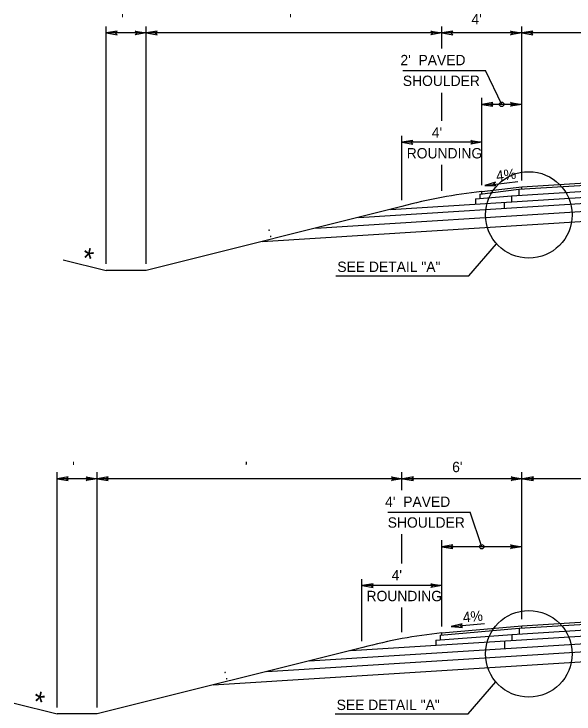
# Model space of a CAD drawing. Extents: x -592 to 1199, y -590 to 416.
# Drawn here: x -145.8 to -70.2, y -200.3 to -105.8 of the extents above; entities that cross this region are included whole.
import ezdxf

# ---------------------------------------------------------------- set-up
doc = ezdxf.new("R2010")
doc.units = 0
doc.layers.add('1', color=7, linetype='Continuous')
doc.layers.add('Des_ Drain_ Ftrs', color=7, linetype='Continuous')

msp = doc.modelspace()

# ---------------------------------------------------------------- linework, layer by layer
at = {"layer": '1'}
for p, q in [((-133.367, -139.572), (-133.367, -107.501)), ((-127.978, -139.572), (-127.978, -107.501)), ((-88.064, -110.502), (-88.064, -107.501)), ((-77.288, -128.298), (-77.288, -107.501)), ((-127.978, -108.381), (-133.367, -108.381)), ((-88.064, -108.381), (-127.978, -108.381)), ((-77.288, -108.381), (-88.064, -108.381)), ((-47.653, -108.381), (-77.288, -108.381)), ((-93.33, -113.449), (-82.189, -113.449)), ((-79.982, -118.031), (-82.189, -113.449)), ((-88.064, -120.251), (-88.064, -116.46)), ((-82.676, -128.932), (-82.676, -117.151)), ((-77.288, -118.031), (-82.676, -118.031)), ((-93.458, -130.942), (-93.458, -122.263)), ((-82.676, -123.143), (-93.453, -123.143)), ((-88.069, -129.71), (-88.069, -126.207)), ((-77.288, -129.176), (-47.653, -127.315)), ((-82.267, -128.973), (-77.799, -128.447)), ((-78.64, -130.37), (-47.653, -128.422)), ((-77.652, -129.499), (-47.653, -127.613)), ((-95.002, -132.208), (-47.653, -129.231)), ((-82.681, -129.813), (-77.288, -129.176)), ((-77.288, -129.476), (-77.288, -129.176)), ((-99.325, -133.288), (-47.653, -130.04)), ((-83.516, -130.803), (-78.64, -130.37)), ((-82.921, -130.142), (-77.652, -129.499)), ((-82.921, -130.142), (-82.921, -130.75)), ((-82.681, -130.113), (-82.681, -129.813)), ((-78.64, -130.37), (-78.64, -131.179)), ((-77.652, -129.499), (-77.652, -130.308)), ((-105.092, -134.73), (-47.653, -131.119)), ((-83.516, -130.803), (-83.516, -131.479)), ((-79.629, -131.241), (-79.629, -132.05)), ((-93.458, -131.822), (-127.978, -140.452)), ((-112.296, -136.531), (-47.653, -132.467)), ((-84.424, -141.157), (-80.685, -136.838)), ((-139.194, -138.995), (-133.367, -140.452)), ((-127.978, -140.452), (-133.367, -140.452)), ((-102.356, -141.157), (-84.424, -141.157)), ((-139.987, -199.449), (-139.987, -167.682)), ((-134.599, -199.449), (-134.599, -167.682)), ((-93.452, -170.111), (-93.452, -167.682)), ((-77.287, -187.549), (-77.287, -167.682)), ((-134.599, -168.562), (-139.987, -168.562)), ((-93.362, -168.562), (-134.599, -168.562)), ((-77.197, -168.562), (-93.362, -168.562)), ((-47.652, -168.562), (-77.197, -168.562)), ((-95.366, -173.077), (-84.225, -173.077)), ((-82.675, -177.748), (-84.225, -173.077)), ((-93.452, -180.019), (-93.452, -176.059)), ((-88.064, -188.506), (-88.064, -176.868)), ((-77.287, -177.748), (-88.064, -177.748)), ((-98.841, -190.512), (-98.841, -182.122)), ((-88.064, -183.002), (-98.84, -183.002)), ((-93.452, -189.283), (-93.452, -185.951)), ((-77.646, -188.746), (-47.652, -186.86)), ((-77.287, -188.423), (-47.652, -186.565)), ((-78.619, -189.603), (-47.652, -187.657)), ((-100.333, -191.765), (-47.652, -188.453)), ((-88.299, -189.707), (-77.646, -188.746)), ((-88.064, -189.386), (-77.287, -188.423)), ((-86.79, -188.513), (-82.309, -188.115)), ((-77.646, -188.746), (-77.646, -189.542)), ((-77.287, -188.723), (-77.287, -188.423)), ((-105.955, -193.17), (-47.652, -189.505)), ((-88.879, -190.361), (-78.619, -189.603)), ((-88.299, -189.707), (-88.299, -190.318)), ((-88.064, -189.686), (-88.064, -189.386)), ((-78.619, -189.603), (-78.619, -190.4)), ((-111.679, -194.601), (-47.652, -190.576)), ((-88.879, -190.361), (-88.879, -191.045)), ((-79.592, -190.461), (-79.592, -191.513)), ((-98.714, -191.36), (-134.599, -200.329)), ((-118.916, -196.41), (-47.652, -191.93)), ((-84.519, -200.298), (-80.779, -195.979)), ((-145.815, -198.873), (-139.987, -200.329)), ((-134.599, -200.329), (-139.987, -200.329)), ((-102.451, -200.298), (-84.519, -200.298))]:
    msp.add_line(p, q, dxfattribs=at)
for centre, radius in [((-79.982, -118.031), 0.3), ((-76.323, -132.955), 5.838), ((-82.675, -177.748), 0.3), ((-76.322, -192.207), 5.838)]:
    msp.add_circle(centre, radius, dxfattribs=at)
for centre, end in [((-75.799, -196.647), 105.23809), ((-81.181, -256.22), 105.12625)]:
    msp.add_arc(centre, 67.188, 95.87953, end, dxfattribs=at)
at = {"layer": 'Des_ Drain_ Ftrs'}
for points in [[(-133.367, -108.381), (-131.878, -108.629), (-132.173, -108.381), (-131.878, -108.133)], [(-127.978, -108.381), (-129.467, -108.629), (-129.172, -108.381), (-129.467, -108.133)], [(-127.978, -108.381), (-126.49, -108.629), (-126.785, -108.381), (-126.49, -108.133)], [(-88.064, -108.381), (-89.553, -108.629), (-89.258, -108.381), (-89.553, -108.133)], [(-88.064, -108.381), (-86.576, -108.629), (-86.871, -108.381), (-86.576, -108.133)], [(-77.288, -108.381), (-78.776, -108.629), (-78.481, -108.381), (-78.776, -108.133)], [(-77.288, -108.381), (-75.799, -108.629), (-76.094, -108.381), (-75.799, -108.133)], [(-82.676, -118.031), (-81.188, -118.28), (-81.483, -118.031), (-81.188, -117.783)], [(-77.288, -118.031), (-78.776, -118.28), (-78.481, -118.031), (-78.776, -117.783)], [(-93.453, -123.143), (-91.964, -123.392), (-92.259, -123.143), (-91.964, -122.895)], [(-82.676, -123.143), (-84.165, -123.392), (-83.87, -123.143), (-84.165, -122.895)], [(-82.267, -128.973), (-80.76, -129.047), (-81.081, -128.834), (-80.817, -128.553)], [(-139.987, -168.562), (-138.499, -168.81), (-138.794, -168.562), (-138.499, -168.314)], [(-134.599, -168.562), (-136.087, -168.81), (-135.792, -168.562), (-136.087, -168.314)], [(-134.599, -168.562), (-133.11, -168.81), (-133.405, -168.562), (-133.11, -168.314)], [(-93.362, -168.562), (-94.851, -168.81), (-94.556, -168.562), (-94.851, -168.314)], [(-93.362, -168.562), (-91.874, -168.81), (-92.169, -168.562), (-91.874, -168.314)], [(-77.197, -168.562), (-78.686, -168.81), (-78.391, -168.562), (-78.686, -168.314)], [(-77.197, -168.562), (-75.709, -168.81), (-76.004, -168.562), (-75.709, -168.314)], [(-88.064, -177.748), (-86.575, -177.996), (-86.87, -177.748), (-86.575, -177.499)], [(-77.287, -177.748), (-78.775, -177.996), (-78.48, -177.748), (-78.775, -177.499)], [(-98.84, -183.002), (-97.352, -183.25), (-97.647, -183.002), (-97.352, -182.754)], [(-88.064, -183.002), (-89.552, -183.25), (-89.257, -183.002), (-89.552, -182.754)], [(-86.79, -188.513), (-85.286, -188.63), (-85.601, -188.408), (-85.329, -188.135)]]:
    msp.add_lwpolyline(points, close=True, dxfattribs=at)

# ---------------------------------------------------------------- texts
at = {"layer": '1'}
for s, p in [(" '", (-131.868, -107.23)), ("  '", (-109.717, -107.23)), ("4'", (-84.066, -107.23)), ("2'  PAVED", (-93.657, -112.749)), ('SHOULDER', (-93.331, -115.549)), ("4'", (-89.417, -122.528)), ('ROUNDING', (-92.806, -125.328)), ('SEE DETAIL "A"', (-102.171, -140.654)), (" '", (-138.488, -167.681)), ("  '", (-115.676, -167.681)), ("6'", (-86.67, -167.681)), ("4'  PAVED", (-95.716, -172.377)), ('SHOULDER', (-95.367, -175.177)), ("4'", (-94.842, -182.302)), ('ROUNDING', (-98.231, -185.102)), ('SEE DETAIL "A"', (-102.265, -199.795))]:
    msp.add_text(s, height=1.4, dxfattribs=at).set_placement(p)
for s, height, rotation, p in [('4%', 1.4, 7.00002, (-80.663, -128.398)), (' : ', 1.4, 14.22821, (-111.898, -136.149)), ('*', 2.8, 347.15207, (-136.881, -140.02)), ('4%', 1.4, 5.3573, (-85.171, -187.984)), (' : ', 1.4, 14.22821, (-117.836, -195.858)), ('*', 2.8, 347.15207, (-143.502, -199.898))]:
    msp.add_text(s, height=height, rotation=rotation, dxfattribs=at).set_placement(p)

doc.saveas('drawing.dxf')
